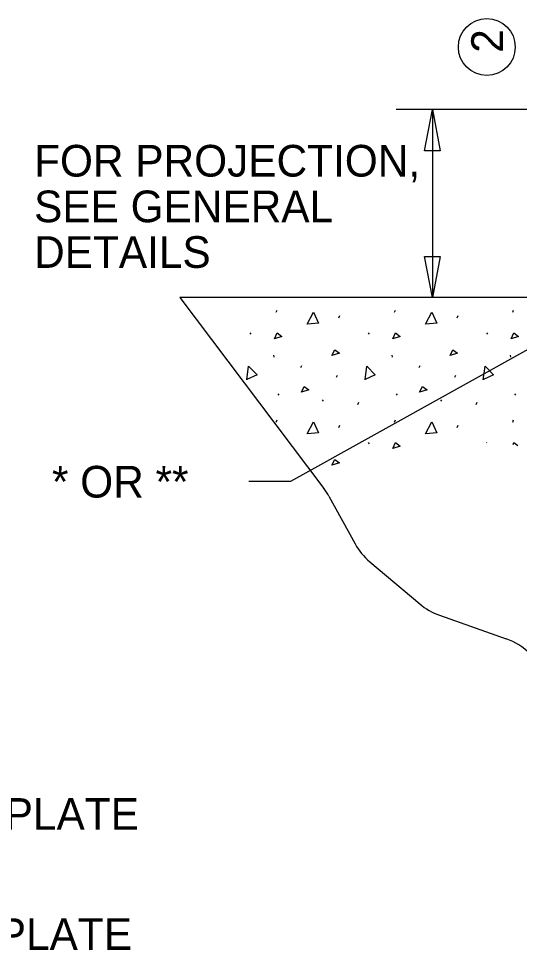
# Model space of a CAD drawing. Extents: x -125.5 to -89.4, y -5.1 to 16.9.
# Drawn here: x -120.383 to -118.408, y 10.396 to 14.074 of the extents above; entities that cross this region are included whole.
import ezdxf

# ---------------------------------------------------------------- set-up
doc = ezdxf.new("R2010")
doc.units = 0
for name, color, linetype in [('BR_AUTO DIMENSION', 7, 'Continuous'), ('BR_CONCRETE', 7, 'Continuous'), ('BR_TEXT', 7, 'Continuous'), ('Default', 7, 'Continuous')]:
    doc.layers.add(name, color=color, linetype=linetype)

msp = doc.modelspace()

# ---------------------------------------------------------------- linework, layer by layer
at = {"layer": 'BR_AUTO DIMENSION'}
for p, q in [((-117.7986, 13.7148), (-118.8938, 13.7148)), ((-118.7513, 13.7148), (-118.7513, 12.9727)), ((-119.3102, 12.2479), (-117.8689, 13.0491)), ((-119.4755, 12.2479), (-119.3102, 12.2479))]:
    msp.add_line(p, q, dxfattribs=at)
for points in [[(-118.7825, 13.5523), (-118.7513, 13.7148), (-118.72, 13.5523)], [(-118.72, 13.1352), (-118.7513, 12.9727), (-118.7825, 13.1352)]]:
    msp.add_lwpolyline(points, close=True, dxfattribs=at)
msp.add_circle((-118.5364, 13.9616), 0.1121, dxfattribs=at)
at = {"layer": 'BR_CONCRETE'}
msp.add_line((-114.1549, 12.9727), (-119.7474, 12.9727), dxfattribs=at)
at = {"layer": 'Default'}
for p, q in [((-119.7474, 12.9727), (-119.1793, 12.2195)), ((-119.3676, 12.9144), (-119.3639, 12.9227)), ((-119.2451, 12.8681), (-119.2201, 12.9153)), ((-119.2201, 12.9153), (-119.2007, 12.8718)), ((-118.901, 12.9144), (-118.8973, 12.9227)), ((-118.7784, 12.8681), (-118.7534, 12.9153)), ((-118.7534, 12.9153), (-118.734, 12.8718)), ((-118.4343, 12.9144), (-118.4306, 12.9227)), ((-119.2007, 12.8718), (-119.2441, 12.8681)), ((-119.1202, 12.8931), (-119.1165, 12.9014)), ((-118.734, 12.8718), (-118.7775, 12.8681)), ((-118.6535, 12.8931), (-118.6498, 12.9014)), ((-119.4712, 12.8339), (-119.4675, 12.8283)), ((-119.3741, 12.8098), (-119.363, 12.833)), ((-119.3445, 12.8191), (-119.3741, 12.8098)), ((-119.363, 12.833), (-119.3445, 12.8191)), ((-119.0046, 12.8339), (-119.0009, 12.8283)), ((-118.9074, 12.8098), (-118.8963, 12.833)), ((-118.8778, 12.8191), (-118.9074, 12.8098)), ((-118.8963, 12.833), (-118.8778, 12.8191)), ((-118.5379, 12.8339), (-118.5342, 12.8283)), ((-118.4408, 12.8098), (-118.4297, 12.833)), ((-118.4112, 12.8191), (-118.4408, 12.8098)), ((-118.4297, 12.833), (-118.4112, 12.8191)), ((-119.1478, 12.7437), (-119.1367, 12.7668)), ((-119.1367, 12.7668), (-119.1182, 12.753)), ((-118.6811, 12.7437), (-118.67, 12.7668)), ((-118.67, 12.7668), (-118.6515, 12.753)), ((-119.3777, 12.7452), (-119.3768, 12.7368)), ((-119.1182, 12.753), (-119.1478, 12.7437)), ((-118.911, 12.7452), (-118.9101, 12.7368)), ((-118.6515, 12.753), (-118.6811, 12.7437)), ((-118.4444, 12.7452), (-118.4434, 12.7368)), ((-119.4836, 12.6486), (-119.4762, 12.7014)), ((-119.4762, 12.7014), (-119.4431, 12.6672)), ((-119.27, 12.6961), (-119.2663, 12.7044)), ((-119.0169, 12.6486), (-119.0096, 12.7014)), ((-119.0096, 12.7014), (-118.9764, 12.6672)), ((-118.8034, 12.6961), (-118.7997, 12.7044)), ((-118.5502, 12.6486), (-118.5429, 12.7014)), ((-118.5429, 12.7014), (-118.5098, 12.6672)), ((-119.4431, 12.6672), (-119.4827, 12.6489)), ((-119.1294, 12.6581), (-119.1257, 12.6665)), ((-118.9764, 12.6672), (-119.016, 12.6489)), ((-118.6628, 12.6581), (-118.6591, 12.6665)), ((-118.5098, 12.6672), (-118.5494, 12.6489)), ((-119.2682, 12.5989), (-119.2571, 12.6221)), ((-119.2571, 12.6221), (-119.2386, 12.6082)), ((-118.8015, 12.5989), (-118.7904, 12.6221)), ((-118.7904, 12.6221), (-118.7719, 12.6082)), ((-119.3606, 12.5925), (-119.3569, 12.5869)), ((-119.2386, 12.6082), (-119.2682, 12.5989)), ((-118.8939, 12.5925), (-118.8902, 12.5869)), ((-118.7719, 12.6082), (-118.8015, 12.5989)), ((-118.4273, 12.5925), (-118.4236, 12.5869)), ((-119.186, 12.5689), (-119.1823, 12.5634)), ((-119.0453, 12.5508), (-119.0416, 12.5592)), ((-118.7193, 12.5689), (-118.7156, 12.5634)), ((-118.5786, 12.5508), (-118.5749, 12.5592)), ((-119.3676, 12.4815), (-119.3639, 12.4898)), ((-119.2451, 12.4353), (-119.2201, 12.4824)), ((-119.2201, 12.4824), (-119.2007, 12.439)), ((-119.1202, 12.4602), (-119.1165, 12.4686)), ((-118.901, 12.4815), (-118.8973, 12.4898)), ((-118.7784, 12.4353), (-118.7534, 12.4824)), ((-118.7534, 12.4824), (-118.734, 12.439)), ((-118.6535, 12.4602), (-118.6498, 12.4686)), ((-118.4343, 12.4815), (-118.4306, 12.4898)), ((-119.2007, 12.439), (-119.2441, 12.4353)), ((-118.734, 12.439), (-118.7775, 12.4353)), ((-119.0046, 12.401), (-119.0009, 12.3955)), ((-118.9074, 12.377), (-118.8963, 12.4001)), ((-118.8963, 12.4001), (-118.8778, 12.3862)), ((-118.5379, 12.401), (-118.5365, 12.3989)), ((-118.433, 12.3932), (-118.4297, 12.4001)), ((-118.4297, 12.4001), (-118.4138, 12.3882)), ((-118.8778, 12.3862), (-118.9074, 12.377)), ((-119.1478, 12.3109), (-119.1367, 12.334)), ((-119.1182, 12.3201), (-119.1478, 12.3109)), ((-119.1367, 12.334), (-119.1182, 12.3201)), ((-119.1597, 12.1893), (-119.0561, 12.0007)), ((-118.9983, 11.9301), (-118.8012, 11.7637)), ((-118.7233, 11.7191), (-118.4605, 11.6261))]:
    msp.add_line(p, q, dxfattribs=at)
for centre, start, end in [((-119.3788, 12.069), 28.7877, 37.0271), ((-118.837, 12.1211), 208.7877, 229.8326), ((-118.6399, 11.9548), 229.8326, 250.5152), ((-118.5438, 11.3904), 44.6646, 70.5152)]:
    msp.add_arc(centre, 0.25, start, end, dxfattribs=at)

# ---------------------------------------------------------------- texts
at = {"layer": 'BR_AUTO DIMENSION'}
msp.add_text('2', height=0.125, rotation=90, dxfattribs=at).set_placement((-118.4728, 13.9389))
at = {"layer": 'BR_TEXT'}
for s, p in [('FOR PROJECTION, ', (-120.3225, 13.4502)), ('SEE GENERAL', (-120.3225, 13.27)), ('DETAILS', (-120.3225, 13.0899)), ('BUILD-DOWN PLATE', (-121.562, 10.8719))]:
    msp.add_text(s, height=0.125, dxfattribs=at).set_placement(p)
for s, p in [('* OR **', (-120.252, 12.1833)), ('BUILD-DOWN PLATE', (-121.5894, 10.3978))]:
    msp.add_text(s, height=0.125, rotation=360, dxfattribs=at).set_placement(p)

doc.saveas('drawing.dxf')
